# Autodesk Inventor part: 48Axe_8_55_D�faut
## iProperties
Created: 2011-01
Part Number: 48Axe_8_55_D�faut
Document SubType Name: Modeling
Designer: eric
Density: 1 g/cm^3
Mass: 2.74156 g
Surface Area: 14.5078 cm^2
Volume: 2.74156 cm^3
Author: eric
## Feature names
1. Base1
